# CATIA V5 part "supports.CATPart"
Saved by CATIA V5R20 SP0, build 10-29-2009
Part number: supports
Source: Unknown
Bounding box of the stored display mesh (mm): x -118.856 to -98.856, y 171.73 to 191.73, z 0 to 60
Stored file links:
  C:\Users\Ikarus\OneDrive - FH JOANNEUM\BAC - Arbeit 1\CAD Modell\CAD-Modell-Step files\Base\supports.CATPart
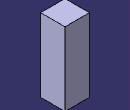
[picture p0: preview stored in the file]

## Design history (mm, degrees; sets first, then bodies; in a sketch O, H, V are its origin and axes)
Body1 (main body)
  Solid1 "Hauptkörper": solid without history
